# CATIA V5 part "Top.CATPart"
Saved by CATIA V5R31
Part number: Part1.1
Bounding box of the stored display mesh (mm): x -50 to 50, y -25 to 25, z -20 to 10
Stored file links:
  D:\PROJECTS\Project 2021\US EDITION\CATIA V5 6R 2021\Resources\Part Files\c12_catia_v5_6r2021_prt\c12_catia_v5-6r2021 figr_12-22\Top.CATPart
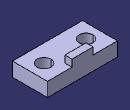
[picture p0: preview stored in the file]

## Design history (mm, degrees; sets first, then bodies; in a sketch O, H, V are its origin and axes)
Body1 (main body)
  Sketch1 on xy-plane, origin (0, 0, 0), H (1, 0, 0), V (0, 1, 0)
    line L1 (50, 25) -> (50, -25)
    line L2 (50, -25) -> (-50, -25)
    line L3 (-50, -25) -> (-50, 25)
    line L4 (-50, 25) -> (50, 25)
    circle A1 centre (-30, 0) radius 10
    point P5 (-30, 0)
    circle A2 centre (30, 0) radius 10
    length L2 = 100
    length L1 = 50
    radius A1 = 10
    distance P5 V = 30
    vertical: L1 V, L3 V
    horizontal: L2 H, L4 H
    equidistance: L1 L3 O, L2 L4 O
    coincidence: P5 H
    symmetry: A1 A2 V
  Pad1: profile Sketch1, direction (0, 0, -1), length 20
  Sketch2 on face of Pad1, origin (0, 0, 0), H (1, 0, 0), V (0, 1, 0)
    line L1 (-15, 25) -> (15, 25)
    line L2 (15, 25) -> (15, 15)
    line L3 (15, 15) -> (-15, 15)
    line L4 (-15, 15) -> (-15, 25)
    reference projected line E1 (50, 25) -> (-50, 25) from edge [face of Pad1 | face of Pad1]
    length L1 = 30
    distance L4 V = 15
    length L2 = 10
    horizontal: L1 H, L3 H
    vertical: L2 V, L4 V
    coincidence: L1 E1
  Pad2: profile Sketch2, direction (0, 0, 1), length 10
